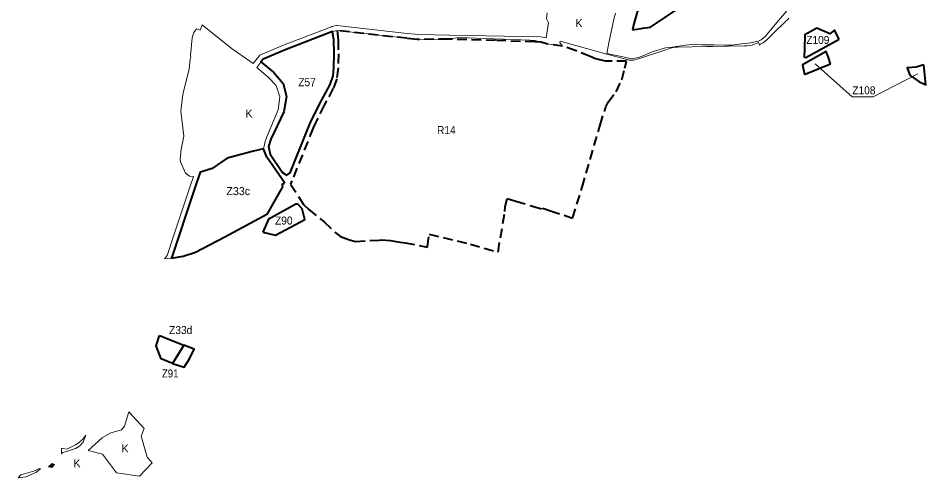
# Model space of a CAD drawing. Extents: x -650276 to -642489, y -1074311 to -1066658.
# Drawn here: x -648979 to -646257, y -1074311 to -1072934 of the extents above; entities that cross this region are included whole.
import ezdxf

# ---------------------------------------------------------------- set-up
doc = ezdxf.new("R2010")
doc.units = 0
doc.header["$LTSCALE"] = 9.6
doc.linetypes.add('MEDIUM_DASHED', pattern=[4.5, 3, -1.5])
for name, color, linetype, lineweight in [('4', 7, 'Continuous', 40), ('44', 7, 'Continuous', 40), ('45', 7, 'Continuous', 40), ('46', 7, 'Continuous', 13), ('47', 7, 'Continuous', 13), ('48', 7, 'Continuous', 35), ('61', 7, 'MEDIUM_DASHED', 40), ('62', 7, 'Continuous', 35)]:
    doc.layers.add(name, color=color, linetype=linetype, lineweight=lineweight)

msp = doc.modelspace()

# ---------------------------------------------------------------- hatches: boundary and pattern name
at = {"layer": '47'}
msp.add_hatch(color=256, dxfattribs=at).paths.add_polyline_path([(-648876.21, -1074268.73), (-648887.619, -1074278.134), (-648877.799, -1074280.64), (-648870.041, -1074271.932)])

# ---------------------------------------------------------------- linework, layer by layer
at = {"layer": '4'}
for points in [[(-647136.39, -1072968.63), (-647110.32, -1072964.56), (-647107.01, -1072964.04), (-647105.4, -1072963.84), (-647082.36, -1072960.95), (-646931.1, -1072857.55), (-646954.51, -1072815.63), (-646954.7, -1072815.232)], [(-647116.33, -1072895.3), (-647132.47, -1072950.4), (-647136.39, -1072968.63)]]:
    msp.add_lwpolyline(points, dxfattribs=at)
at = {"layer": '44'}
msp.add_line((-648245.341, -1073575.152), (-648207, -1073584), dxfattribs=at)
for points in [[(-648139.56, -1073491.4), (-648146.4, -1073491.55), (-648220.42, -1073532.43), (-648227.63, -1073535.89), (-648245.341, -1073575.152)], [(-648207, -1073584), (-648119, -1073537), (-648127.31, -1073505.75), (-648138.41, -1073493.62), (-648139.56, -1073491.4)]]:
    msp.add_lwpolyline(points, dxfattribs=at)
msp.add_lwpolyline([(-648515.333, -1073968.584), (-648480.86, -1073980.25), (-648464.44, -1073954.69), (-648451.05, -1073925.87), (-648481.749, -1073913.76), (-648498, -1073940)], close=True, dxfattribs=at)
at = {"layer": '45'}
for points in [[(-646516.7, -1072996.65), (-646531.46, -1072970.12), (-646544.68, -1072980.62), (-646584.23, -1072964.22), (-646619.48, -1072984.34), (-646620.71, -1073025.49), (-646621.44, -1073049.79), (-646616.55, -1073052.21)], [(-646516.7, -1072996.65), (-646531.46, -1072970.12), (-646544.68, -1072980.62), (-646584.23, -1072964.22), (-646619.48, -1072984.34), (-646620.71, -1073025.49), (-646621.44, -1073049.79), (-646616.55, -1073052.21)], [(-648554.42, -1073885.092), (-648481.749, -1073913.76), (-648515.333, -1073968.584), (-648549.76, -1073954.86), (-648564.75, -1073915.91)]]:
    msp.add_lwpolyline(points, close=True, dxfattribs=at)
for points in [[(-648030.86, -1073039.71), (-648032.09, -1072998.65), (-648035.592, -1072974.222), (-648175.061, -1073027.551), (-648244.214, -1073056.657), (-648250.491, -1073064.698), (-648212.22, -1073096.39), (-648184.37, -1073129.89)], [(-648030.86, -1073039.71), (-648032.09, -1072998.65), (-648035.592, -1072974.222), (-648175.061, -1073027.551), (-648244.214, -1073056.657), (-648250.491, -1073064.698), (-648212.22, -1073096.39), (-648184.37, -1073129.89)], [(-648101.67, -1073246.63), (-648075.34, -1073191.93), (-648043.29, -1073132.97), (-648034.43, -1073107.07), (-648031.8, -1073082.07), (-648030.86, -1073039.71)], [(-648101.67, -1073246.63), (-648075.34, -1073191.93), (-648043.29, -1073132.97), (-648034.43, -1073107.07), (-648031.8, -1073082.07), (-648030.86, -1073039.71)], [(-646542.62, -1073071.1), (-646550.01, -1073048.55), (-646552.79, -1073041.53), (-646555.79, -1073033.92), (-646624.69, -1073072.66), (-646626.967, -1073073.918), (-646621.38, -1073102.66)], [(-646542.62, -1073071.1), (-646550.01, -1073048.55), (-646552.79, -1073041.53), (-646555.79, -1073033.92), (-646624.69, -1073072.66), (-646626.967, -1073073.918), (-646621.38, -1073102.66)], [(-646542.62, -1073071.1), (-646550.01, -1073048.55), (-646552.79, -1073041.53), (-646555.79, -1073033.92), (-646624.69, -1073072.66), (-646626.967, -1073073.918), (-646621.38, -1073102.66)], [(-646542.62, -1073071.1), (-646550.01, -1073048.55), (-646552.79, -1073041.53), (-646555.79, -1073033.92), (-646624.69, -1073072.66), (-646626.967, -1073073.918), (-646621.38, -1073102.66)], [(-646621.38, -1073102.66), (-646620.19, -1073102.14), (-646618.56, -1073101.42), (-646542.62, -1073071.1)], [(-646621.38, -1073102.66), (-646620.19, -1073102.14), (-646618.56, -1073101.42), (-646542.62, -1073071.1)], [(-646621.38, -1073102.66), (-646620.19, -1073102.14), (-646618.56, -1073101.42), (-646542.62, -1073071.1)], [(-646621.38, -1073102.66), (-646620.19, -1073102.14), (-646618.56, -1073101.42), (-646542.62, -1073071.1)], [(-646262.94, -1073074.15), (-646285.77, -1073081.01), (-646312.87, -1073082.4), (-646305.18, -1073104.8), (-646278.38, -1073123.25)], [(-646262.94, -1073074.15), (-646285.77, -1073081.01), (-646312.87, -1073082.4), (-646305.18, -1073104.8), (-646278.38, -1073123.25)], [(-646278.38, -1073123.25), (-646257.09, -1073134.01), (-646262.94, -1073074.15)], [(-646278.38, -1073123.25), (-646257.09, -1073134.01), (-646262.94, -1073074.15)], [(-648184.37, -1073129.89), (-648174.03, -1073168.94), (-648182.12, -1073214.56), (-648221.39, -1073296.24), (-648227.75, -1073318.75), (-648223.03, -1073341.59), (-648186.47, -1073396.47), (-648173.38, -1073404.03)], [(-648184.37, -1073129.89), (-648174.03, -1073168.94), (-648182.12, -1073214.56), (-648221.39, -1073296.24), (-648227.75, -1073318.75), (-648223.03, -1073341.59), (-648186.47, -1073396.47), (-648173.38, -1073404.03)], [(-648173.38, -1073404.03), (-648162.55, -1073397.4), (-648112.36, -1073270.87), (-648101.67, -1073246.63)], [(-648173.38, -1073404.03), (-648162.55, -1073397.4), (-648112.36, -1073270.87), (-648101.67, -1073246.63)], [(-648179.07, -1073428.81), (-648233.36, -1073350.68), (-648243.08, -1073325.04), (-648272.642, -1073332.558)], [(-648179.07, -1073428.81), (-648233.36, -1073350.68), (-648243.08, -1073325.04), (-648272.642, -1073332.558)], [(-648272.642, -1073332.558), (-648352.312, -1073353), (-648397.062, -1073384.375)], [(-648272.642, -1073332.558), (-648352.312, -1073353), (-648397.062, -1073384.375)], [(-648397.062, -1073384.375), (-648432.187, -1073395.625), (-648433.206, -1073395.51), (-648449.599, -1073445.278)], [(-648397.062, -1073384.375), (-648432.187, -1073395.625), (-648433.206, -1073395.51), (-648449.599, -1073445.278)], [(-648447.06, -1073635.39), (-648358.69, -1073589.35), (-648230.81, -1073520.18), (-648185.34, -1073438.91), (-648185.82, -1073435.12), (-648186.46, -1073430.01), (-648183.46, -1073429.52), (-648179.07, -1073428.81)], [(-648447.06, -1073635.39), (-648358.69, -1073589.35), (-648230.81, -1073520.18), (-648185.34, -1073438.91), (-648185.82, -1073435.12), (-648186.46, -1073430.01), (-648183.46, -1073429.52), (-648179.07, -1073428.81)], [(-648449.599, -1073445.278), (-648518.867, -1073652.836), (-648483.58, -1073646.7), (-648447.06, -1073635.39), (-648447.06, -1073635.39)], [(-648449.599, -1073445.278), (-648518.867, -1073652.836), (-648483.58, -1073646.7), (-648447.06, -1073635.39), (-648447.06, -1073635.39)]]:
    msp.add_lwpolyline(points, dxfattribs=at)
at = {"layer": '46'}
msp.add_lwpolyline([(-646588.523, -1073070.963), (-646477.555, -1073169.273), (-646414.561, -1073169.273), (-646281.126, -1073101.085)], dxfattribs=at)
msp.add_lwpolyline([(-646588.523, -1073070.963), (-646477.555, -1073169.273), (-646414.561, -1073169.273), (-646281.126, -1073101.085)], dxfattribs=at)
at = {"layer": '47'}
for points in [[(-646653.846, -1072889.44), (-646692.432, -1072934.135), (-646739.241, -1072988.798), (-646751.061, -1072999.106), (-646758.883, -1073002.885), (-646760.416, -1073003.25), (-646781.703, -1073007.452), (-646809.778, -1073011.019), (-646838.25, -1073014.938), (-646861.07, -1073014.672), (-646890.523, -1073014.073), (-646904.131, -1073013.793), (-646914.796, -1073013.573), (-646918.156, -1073013.511), (-646928.807, -1073013.313), (-646956.919, -1073012.775), (-646978.077, -1073014.931), (-646997.824, -1073018.092), (-647006.715, -1073019.236), (-647009.402, -1073019.582), (-647026.763, -1073021.811), (-647037.971, -1073023.24), (-647060.677, -1073029.351), (-647064.784, -1073030.747), (-647082.267, -1073036.684), (-647097.466, -1073044.268), (-647118.513, -1073051.327), (-647134.596, -1073054.974), (-647143.312, -1073055.421), (-647147.85, -1073054.204), (-647152.621, -1073052.925), (-647154.999, -1073052.287), (-647161.068, -1073050.946), (-647161.068, -1073050.946), (-647161.068, -1073050.946), (-647213.218, -1073039.42), (-647213.562, -1073039.322), (-647210.396, -1073023.593), (-647207.176, -1073007.598), (-647192.93, -1072936.82), (-647187.445, -1072918.804)], [(-647392.96, -1072918.277), (-647394.87, -1072936.08), (-647388.62, -1072948.03), (-647395.47, -1072993.25), (-647411.293, -1072989.813), (-647411.294, -1072989.813), (-647411.294, -1072989.813), (-647411.298, -1072989.813), (-647685.748, -1072984.544), (-647778.296, -1072982.767), (-647811.752, -1072979.4), (-648023.495, -1072955.875), (-648023.498, -1072955.876), (-648023.818, -1072955.949), (-648037.595, -1072959.123), (-648038.877, -1072959.418), (-648180.651, -1073013.629), (-648253.635, -1073044.348), (-648261.902, -1073054.939), (-648273.756, -1073070.132), (-648273.756, -1073070.132), (-648339.58, -1073023.82), (-648341.495, -1073022.285), (-648411.09, -1072966.5), (-648426.547, -1072954.108)], [(-646754.581, -1073015.554), (-646753.573, -1073012.306), (-646744.92, -1073007.46), (-646732.95, -1072998.07), (-646710.3, -1072975.31), (-646680.07, -1072945.74), (-646668.53, -1072935.52), (-646669.198, -1072934.569), (-646668.09, -1072933.43)], [(-648426.547, -1072954.108), (-648432.527, -1072969.463), (-648443.591, -1072965.983), (-648451.657, -1072977.25), (-648456.2, -1072989.149), (-648457.123, -1072993.118), (-648461.979, -1073045.585), (-648460.355, -1073048.753), (-648461.973, -1073052.688), (-648463.036, -1073057.011), (-648465.708, -1073085.876), (-648484.661, -1073162.812), (-648490.539, -1073212.35), (-648481.853, -1073287.675), (-648489.355, -1073326.567), (-648492.485, -1073357.358), (-648491.34, -1073364.805), (-648477.028, -1073398.055), (-648464.929, -1073407.031), (-648453.228, -1073408.349), (-648463.838, -1073440.559), (-648513.627, -1073589.927), (-648532.252, -1073645.567), (-648539.599, -1073654.802), (-648531.31, -1073654.08), (-648522.79, -1073653.23), (-648518.867, -1073652.836), (-648499.399, -1073594.679), (-648449.599, -1073445.278), (-648433.206, -1073395.51), (-648432.187, -1073395.625), (-648397.062, -1073384.375), (-648378.125, -1073370.875), (-648352.312, -1073353), (-648314.687, -1073343.25), (-648272.642, -1073332.558), (-648243.08, -1073325.04), (-648237.98, -1073303.4), (-648232.64, -1073289.31), (-648198.7, -1073209.08), (-648194.2, -1073170.13), (-648205.04, -1073136.07), (-648228.91, -1073110.54), (-648262.917, -1073081.543), (-648251.027, -1073065.418), (-648250.491, -1073064.698), (-648244.214, -1073056.657), (-648175.061, -1073027.551), (-648035.592, -1072974.222), (-648022.279, -1072971.102), (-647813.331, -1072994.317), (-647782.72, -1072997.397), (-647777.337, -1072997.711), (-647689.11, -1072996.49), (-647658.437, -1072991.865), (-647658.437, -1072991.865), (-647658.437, -1072991.865), (-647658.437, -1072991.865), (-647658.437, -1072991.865), (-647658.437, -1072991.865), (-647497.35, -1072997.93), (-647444.42, -1072999.87), (-647429.276, -1073000.424), (-647411.34, -1073005.89), (-647394.782, -1073011.002), (-647346.22, -1073017.52), (-647354.76, -1073006.65), (-647353.78, -1073003.1), (-647213.99, -1073041.449), (-647153.44, -1073058.06), (-647152.96, -1073058.19), (-647147.91, -1073059.64), (-647147.43, -1073059.78), (-647147.17, -1073059.97), (-647134.03, -1073059.94), (-647118.27, -1073055.88), (-647033.44, -1073027.43), (-647028.91, -1073025.91), (-647026.54, -1073025.11), (-647013.4, -1073021.42), (-647006.15, -1073020.99), (-647001.66, -1073020.72), (-646914.54, -1073019), (-646913.94, -1073018.99), (-646899.22, -1073018.7), (-646895.76, -1073018.63), (-646800.44, -1073016.74), (-646793.8, -1073016.61), (-646777.74, -1073015.29), (-646758.545, -1073007.234), (-646755.58, -1073013.43), (-646754.581, -1073015.554)], [(-648833.449, -1074232.685), (-648807.065, -1074223.704), (-648794.902, -1074216.219), (-648783.863, -1074204.056), (-648775.93, -1074183.91), (-648784.8, -1074195.26), (-648795.65, -1074205.35), (-648806.55, -1074212.62), (-648833.11, -1074225.2), (-648844.05, -1074223.24), (-648848.28, -1074222.49), (-648848.696, -1074238.993)], [(-648848.696, -1074238.993), (-648845.424, -1074235.305), (-648833.449, -1074232.685)]]:
    msp.add_lwpolyline(points, dxfattribs=at)
for points in [[(-648725.93, -1074240.58), (-648683.5, -1074296.12), (-648683.5, -1074296.12), (-648614.6, -1074306.17), (-648577.25, -1074266.06), (-648591.67, -1074249.72), (-648609.49, -1074186.61), (-648600.53, -1074163.47), (-648646.42, -1074113.19), (-648660.16, -1074156.75), (-648669.01, -1074167.27), (-648700.45, -1074176.73), (-648726.23, -1074192.02), (-648747.74, -1074210.12), (-648768.94, -1074229.25)], [(-648876.21, -1074268.73), (-648887.619, -1074278.134), (-648877.799, -1074280.64), (-648870.041, -1074271.932)], [(-648978.575, -1074311.426), (-648955.265, -1074308.325), (-648923.698, -1074294.313), (-648912.63, -1074284.912), (-648910.988, -1074284.211), (-648915.73, -1074283.08), (-648929.03, -1074290.14), (-648970.3, -1074302.9)]]:
    msp.add_lwpolyline(points, close=True, dxfattribs=at)
at = {"layer": '61'}
msp.add_lwpolyline([(-648019.38, -1072999.62), (-648018.59, -1073040.65), (-648019.04, -1073082.7), (-648023.38, -1073115.63), (-648033.71, -1073143.76), (-648060.75, -1073194.72), (-648088.41, -1073249.9), (-648094.092, -1073263.034), (-648157.74, -1073420.89), (-648161.7, -1073431.46), (-648127.64, -1073484.76), (-648122.58, -1073492.69), (-648107.53, -1073507.68), (-648060.92, -1073544.52), (-648027.7, -1073575.75), (-648012.55, -1073588.03), (-647987.9, -1073597.16), (-647967.15, -1073602.95), (-647896.59, -1073598.78), (-647889.64, -1073598.65), (-647861.92, -1073599.87), (-647840.12, -1073604.27), (-647818.3, -1073607.2), (-647751.31, -1073619.66), (-647751.124, -1073618.122), (-647746.63, -1073580.97), (-647622.63, -1073611.03), (-647539.83, -1073634.79), (-647519.11, -1073513.63), (-647518.27, -1073499.08), (-647511.932, -1073474.5), (-647486.04, -1073482.326), (-647436.7, -1073497.24), (-647406.33, -1073506.42), (-647405.5, -1073503.75), (-647382.45, -1073511.28), (-647316.269, -1073532.9), (-647287.03, -1073440.3), (-647233.5, -1073254.63), (-647218, -1073203.36), (-647216.34, -1073199.89), (-647209.63, -1073185.84), (-647185.73, -1073154.33), (-647168.83, -1073118.8), (-647159.72, -1073083.31), (-647154.77, -1073062.68), (-647218.06, -1073062.37), (-647247.46, -1073055.63), (-647263.8, -1073049), (-647305.94, -1073031.89), (-647346.22, -1073017.52), (-647394.782, -1073011.002), (-647411.34, -1073005.89), (-647429.65, -1073005.19), (-647547.02, -1073001.04), (-647689.11, -1072996.49), (-647777.336, -1072997.711), (-647782.72, -1072997.397), (-647813.331, -1072994.317), (-648022.279, -1072971.102)], close=True, dxfattribs=at)

# ---------------------------------------------------------------- texts
at = {"layer": '44'}
for s, width, p in [('Z90', 0.95, (-648208.451, -1073552.422)), ('Z90', 0.95, (-648208.451, -1073552.422)), ('Z91', 0.9, (-648547.629, -1074010.653))]:
    msp.add_text(s, height=24, dxfattribs=dict(at, width=width)).set_placement(p)
at = {"layer": '46', "width": 0.95}
for s, p in [('Z109', (-646615.842, -1073011.142)), ('Z109', (-646615.842, -1073011.142)), ('Z57', (-648138.747, -1073137.744)), ('Z57', (-648138.747, -1073137.744)), ('Z108', (-646477.565, -1073162.229)), ('Z108', (-646477.565, -1073162.229)), ('Z33d', (-648525.981, -1073880.565))]:
    msp.add_text(s, height=24, dxfattribs=at).set_placement(p)
at = {"layer": '46'}
msp.add_text('Z33c', height=24, dxfattribs=at).set_placement((-648354.418, -1073464.218))
msp.add_text('Z33c', height=24, dxfattribs=at).set_placement((-648354.418, -1073464.218))
at = {"layer": '48'}
for p in [(-647307.985, -1072960.845), (-647307.985, -1072960.845), (-648296.955, -1073231.892), (-648668.641, -1074235.329), (-648812.985, -1074279.86)]:
    msp.add_text('K', height=24, dxfattribs=at).set_placement(p)
at = {"layer": '62', "width": 0.95}
msp.add_text('R14', height=24, dxfattribs=at).set_placement((-647722.71, -1073281.294))

doc.saveas('drawing.dxf')
